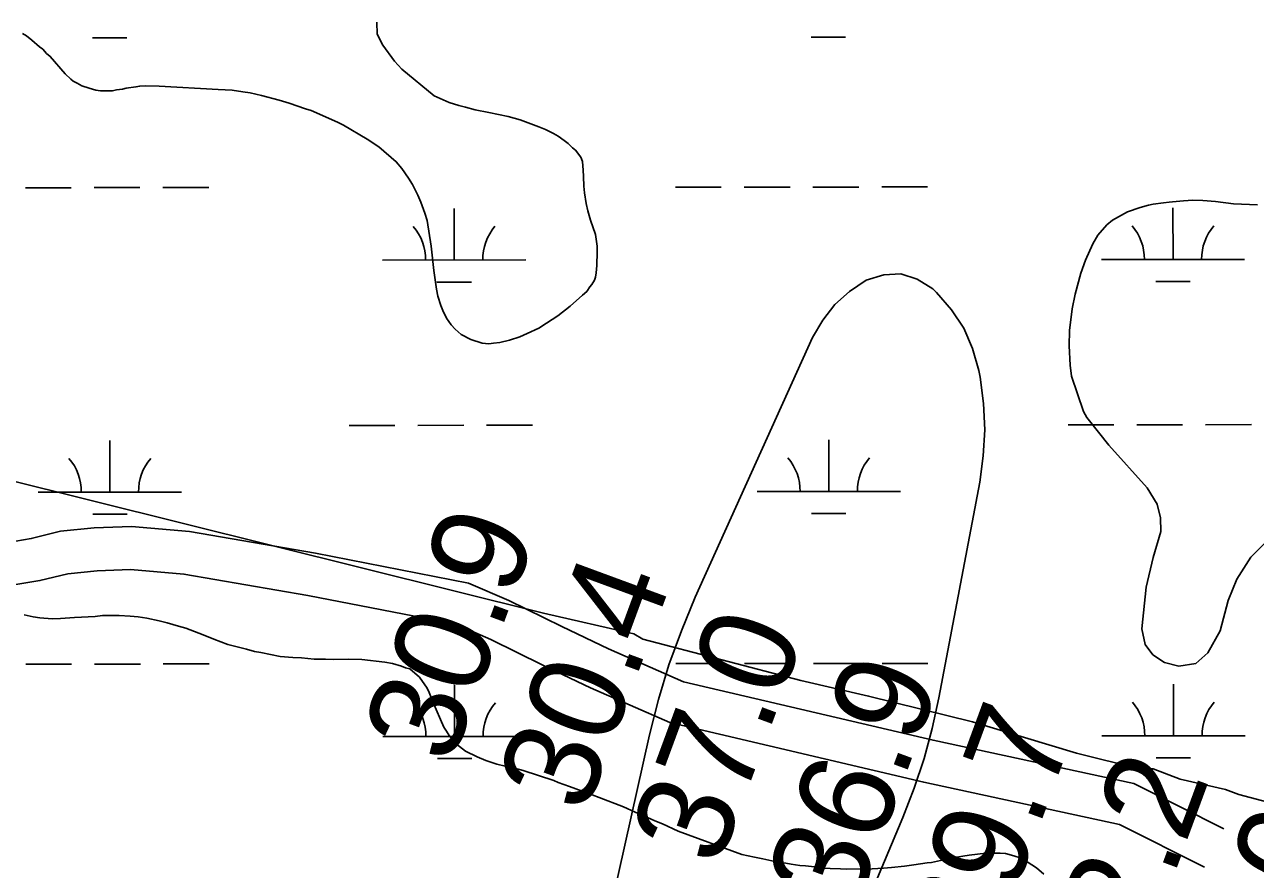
# Model space of a CAD drawing. Extents: x 3297716 to 3335574, y 688621 to 713991.
# Drawn here: x 3319550 to 3320409, y 696104 to 696694 of the extents above; entities that cross this region are included whole.
import ezdxf

# ---------------------------------------------------------------- set-up
doc = ezdxf.new("R2010")
doc.units = 0
for name, color, linetype in [('V-RIVR-EDGE', 7, 'Continuous'), ('V-RIVR-RANG', 7, 'Continuous'), ('V-ROAD-CNTR', 7, 'Continuous'), ('V-SITE-VEGE', 7, 'Continuous'), ('V-TOPO-MINR', 7, 'Continuous'), ('V-UTIL-LINE', 7, 'Continuous'), ('V-WETL-SWMP', 7, 'Continuous')]:
    doc.layers.add(name, color=color, linetype=linetype)

msp = doc.modelspace()

# ---------------------------------------------------------------- linework, layer by layer
at = {"layer": 'V-RIVR-EDGE'}
msp.add_spline([(3321618.45, 701061.3), (3321639.17, 701040.92), (3321661.92, 701020.55), (3321674.32, 701007.67), (3321694.16, 700986.07), (3321717.72, 700957.41), (3321720.61, 700953.26), (3321724.75, 700950.76), (3321726.82, 700949.51), (3321730.12, 700946.19), (3321742.93, 700927.09), (3321753.65, 700905.93), (3321756.11, 700893.9), (3321759.81, 700884.36), (3321768.06, 700867.34), (3321776.73, 700853.23), (3321786.64, 700837.46), (3321794.49, 700827.9), (3321804.41, 700817.1), (3321812.69, 700810.04), (3321821.8, 700809.18), (3321830.09, 700806.68), (3321833.39, 700803.77), (3321835.87, 700798.79), (3321840.83, 700792.97), (3321849.52, 700787.56), (3321852, 700783.83), (3321866.46, 700765.14), (3321875.54, 700751.02), (3321880.08, 700741.06), (3321885.01, 700725.72), (3321889.55, 700717), (3321895.75, 700710.35), (3321901.94, 700699.15), (3321908.12, 700684.63), (3321912.22, 700664.31), (3321919.16, 700623.67), (3321922, 700598.79), (3321922.33, 700564.8), (3321921.8, 700517.55), (3321919.28, 700502.22), (3321912.99, 700476.13), (3321905.84, 700433.04), (3321899.49, 700379.59), (3321893.61, 700348.1), (3321887.31, 700316.2), (3321880.2, 700288.86), (3321874.74, 700259.03), (3321869.25, 700218.84), (3321863.73, 700164.56), (3321860.77, 700141.35), (3321859.51, 700133.9), (3321857.38, 700109.86), (3321857.72, 700080.85), (3321854.3, 700038.58), (3321847.95, 699987.61), (3321847.83, 699937.46), (3321848.6, 699913.83), (3321849.33, 699873.21), (3321853.78, 699830.51), (3321854.96, 699803.15), (3321853.26, 699786.99), (3321851.54, 699762.54), (3321847.36, 699747.63), (3321844.45, 699743.9), (3321843.17, 699728.57), (3321839.41, 699718.22), (3321831.1, 699708.71), (3321827.36, 699705.81), (3321826.94, 699701.67), (3321826.9, 699687.16), (3321823.15, 699678.88), (3321813.6, 699670.62), (3321798.66, 699664.44), (3321785.76, 699644.16), (3321779.93, 699632.57), (3321773.21, 699598.6), (3321768.1, 699540.58), (3321765.15, 699519.86), (3321762.59, 699492.93), (3321757.53, 699458.54), (3321751.27, 699439.49), (3321741.26, 699415.47), (3321732.08, 699391.04), (3321722.08, 699368.27), (3321716.24, 699354.61), (3321712.46, 699334.72), (3321711.17, 699313.17), (3321708.16, 699269.24), (3321710.2, 699258.88), (3321713.08, 699250.99), (3321718.86, 699240.62), (3321727.54, 699231.89), (3321733.75, 699226.9), (3321735.8, 699219.85), (3321729.5, 699186.29), (3321720.32, 699159.37), (3321709.07, 699134.53), (3321700.31, 699115.49), (3321685.36, 699100.6), (3321679.12, 699094.4), (3321674.96, 699087.37), (3321674.54, 699083.64), (3321670.34, 699063.75), (3321660.32, 699031.86), (3321651.17, 699018.62), (3321638.28, 699002.49), (3321632.02, 698987.58), (3321625.76, 698968.12), (3321619.46, 698936.22), (3321615.66, 698908.04), (3321607.29, 698875.32), (3321593.49, 698825.61), (3321583.49, 698805.33), (3321580.14, 698792.07), (3321580.11, 698777.57), (3321580.08, 698768.03), (3321572.16, 698748.16), (3321567.94, 698717.91), (3321559.1, 698663.64), (3321555.74, 698647.06), (3321554.07, 698638.36), (3321550.73, 698631.74), (3321551.53, 698617.65), (3321548.59, 698601.9), (3321548.13, 698586.15), (3321543.97, 698577.46), (3321538.14, 698566.28), (3321534.37, 698551.37), (3321535.17, 698541.42), (3321533.49, 698532.72), (3321521.4, 698502.08), (3321503.45, 698451.14), (3321490.53, 698421.75), (3321481.38, 698409.33), (3321476.81, 698403.96), (3321474.3, 698395.26), (3321466.79, 698374.55), (3321458.45, 698355.09), (3321454.28, 698343.91), (3321453.02, 698339.36), (3321455.92, 698336.45), (3321456.74, 698333.13), (3321454.65, 698329.4), (3321448.83, 698321.96), (3321440.11, 698313.69), (3321430.98, 698308.32), (3321420.6, 698301.3), (3321418.1, 698296.34), (3321412.68, 698284.33), (3321407.28, 698277.71), (3321395.61, 698252.46), (3321375.16, 698198.21), (3321359.31, 698158.46), (3321345.97, 698126.16), (3321337.19, 698093.85), (3321334.25, 698078.94), (3321334.23, 698070.24), (3321336.69, 698059.45), (3321328.74, 698032.12), (3321314.56, 697996.09), (3321306.62, 697968.76), (3321301.21, 697958.41), (3321293.31, 697951.38), (3321284.15, 697933.99), (3321274.57, 697915.37), (3321271.23, 697904.6), (3321272.45, 697893.82), (3321272.42, 697881.8), (3321266.57, 697862.33), (3321256.95, 697828.37), (3321254.44, 697817.6), (3321249.85, 697808.08), (3321241.51, 697787.79), (3321233.61, 697774.54), (3321226.53, 697762.13), (3321220.27, 697745.56), (3321216.1, 697733.97), (3321215.67, 697727.34), (3321217.73, 697725.67), (3321219.8, 697723.6), (3321219.37, 697718.62), (3321208.12, 697691.71), (3321197.7, 697668.11), (3321194.79, 697666.04), (3321191.06, 697666.05), (3321191.45, 697656.52), (3321188.95, 697651.55), (3321185.63, 697649.07), (3321180.24, 697647.84), (3321181.04, 697635.82), (3321179.37, 697630.85), (3321174.8, 697625.89), (3321172.29, 697619.26), (3321170.2, 697612.22), (3321164.33, 697585.71), (3321162.65, 697577.01), (3321158.92, 697575.78), (3321154.35, 697570.81), (3321148.51, 697557.56), (3321144.77, 697550.53), (3321143.91, 697539.34), (3321140.58, 697535.62), (3321134.77, 697529.41), (3321132.68, 697525.27), (3321128.5, 697509.53), (3321122.64, 697486.75), (3321103.06, 697447.42), (3321100.98, 697441.63), (3321100.95, 697432.92), (3321091.79, 697415.12), (3321084.3, 697404.36), (3321071.4, 697382.01), (3321064.34, 697376.64), (3321056.87, 697372.93), (3321048.14, 697363.42), (3321041.07, 697351), (3321031.9, 697332.37), (3321023.56, 697312.08), (3321015.63, 697288.06), (3321006.43, 697254.51), (3320994.76, 697229.67), (3320983.51, 697207.32), (3320979.36, 697203.6), (3320975.6, 697193.66), (3320968.09, 697172.54), (3320962.64, 697145.61), (3320955.95, 697122.42), (3320943.84, 697086.8), (3320940.48, 697069.4), (3320936.31, 697061.12), (3320926.34, 697048.71), (3320920.93, 697043.34), (3320909.64, 697002.33), (3320899.61, 696969.2), (3320887.51, 696935.24), (3320880.84, 696920.33), (3320879.58, 696912.46), (3320883.28, 696900.43), (3320882.85, 696894.63), (3320876.18, 696878.07), (3320871.56, 696854.04), (3320866.95, 696835.81), (3320859.86, 696815.94), (3320857.35, 696806.82), (3320853.17, 696794.4), (3320849.83, 696784.46), (3320847.3, 696766.64), (3320843.13, 696755.46), (3320836.06, 696746.78), (3320830.23, 696736.43), (3320825.62, 696714.06), (3320819.78, 696699.98), (3320814.39, 696700.82), (3320813.53, 696688.39), (3320798.51, 696648.22), (3320788.51, 696625.45), (3320782.7, 696621.73), (3320776.44, 696606.83), (3320773.11, 696599.38), (3320766.05, 696592.76), (3320752.32, 696573.31), (3320739.41, 696550.14), (3320720.25, 696512.05), (3320700.68, 696473.55), (3320668.58, 696401.51), (3320646.49, 696351.83), (3320619.82, 696291.38), (3320606.9, 696264.05), (3320587.72, 696216.85), (3320576.88, 696191.59), (3320559.79, 696152.26), (3320552.68, 696128.24), (3320546.41, 696106.29), (3320536.39, 696076.47), (3320526.77, 696040.43), (3320506.73, 695984.11), (3320462.47, 695850.34), (3320450.34, 695806.02), (3320441.99, 695784.08), (3320420.24, 695702.06), (3320413.95, 695672.23), (3320409.31, 695639.92), (3320408.02, 695624.17), (3320406.74, 695608.42), (3320408.37, 695594.32), (3320410.83, 695583.96), (3320416.18, 695571.92), (3320421.98, 695567.35), (3320430.26, 695563.18), (3320436.88, 695558.19), (3320439.76, 695552.38), (3320445.95, 695539.93), (3320448.82, 695529.15), (3320449.62, 695514.64), (3320448.35, 695507.18), (3320445.85, 695499.32), (3320439.61, 695490.63), (3320432.95, 695478.62), (3320425.04, 695464.14), (3320423.36, 695454.61), (3320416.68, 695438.87), (3320407.94, 695423.56), (3320400.05, 695416.95), (3320392.16, 695411.99), (3320377.64, 695405.4), (3320369.77, 695408.32), (3320357.76, 695410.42), (3320346.57, 695411.28), (3320320.43, 695400.15), (3320298.01, 695386.53), (3320249, 695343.13), (3320201.63, 695295.58), (3320188.34, 695286.49), (3320177.97, 695282.37), (3320168.43, 695279.5), (3320163.44, 695274.95), (3320158.02, 695258.8), (3320150.48, 695228.14), (3320140.07, 695207.45), (3320125.48, 695174.32), (3320115.05, 695149.48), (3320110.04, 695134.99), (3320108.37, 695129.6), (3320108.36, 695125.87), (3320112.48, 695115.91), (3320113.71, 695108.45), (3320113.28, 695102.65), (3320106.62, 695091.47), (3320104.12, 695086.92), (3320100.38, 695081.54), (3320098.3, 695077.82), (3320098.29, 695074.91), (3320104.89, 695063.71), (3320105.7, 695055.41), (3320108.15, 695041.32), (3320112.69, 695030.11), (3320122.19, 695016.41), (3320128.39, 695010.18), (3320133.76, 695004.36), (3320135.82, 694999.39), (3320135.81, 694993.17), (3320132.46, 694981.16), (3320110.39, 694941.42), (3320095, 694917.83), (3320080.04, 694902.95), (3320068.41, 694893.44), (3320055.95, 694881.45), (3320033.07, 694848.77), (3319991.89, 694787.94), (3319966.93, 694752.36), (3319939.88, 694710.15), (3319919.91, 694678.69), (3319900.35, 694647.24), (3319884.95, 694618.27), (3319831.21, 694511.88), (3319802.89, 694453.92), (3319782.47, 694411.28), (3319716.3, 694301.19), (3319680.91, 694240.35), (3319651.35, 694187.37), (3319580.16, 694059.05), (3319556.78, 694017.46)], degree=3, dxfattribs=at)
at = {"layer": 'V-ROAD-CNTR'}
for points in [[(3319258.98, 696423.67), (3319303.18, 696420.44), (3319359.75, 696407.56), (3319427.13, 696378.13), (3319493.56, 696347.28), (3319522.29, 696338.92), (3319543.92, 696333.5), (3319554.75, 696335.31), (3319575.26, 696340.4), (3319598.65, 696342.78), (3319624.79, 696343.71), (3319665.22, 696340.25), (3319753.28, 696325.06), (3319860.04, 696304.26), (3319888.31, 696292.15), (3319925.18, 696273.99), (3319957.8, 696258.37), (3320010.26, 696235.36), (3320184.45, 696194.42), (3320324.59, 696164.24), (3320387.39, 696132.69)], [(3319256.79, 696393.75), (3319298.74, 696390.69), (3319350.33, 696378.94), (3319414.81, 696350.77), (3319482.99, 696319.11), (3319514.45, 696309.96), (3319542.7, 696302.88), (3319560.85, 696305.91), (3319580.42, 696310.77), (3319600.71, 696312.84), (3319624.04, 696313.66), (3319661.38, 696310.47), (3319747.86, 696295.55), (3319851.17, 696275.43), (3319875.76, 696264.88), (3319912.07, 696247), (3319945.29, 696231.09), (3320000.73, 696206.78), (3320177.86, 696165.15), (3320314.54, 696135.71), (3320373.92, 696105.88)]]:
    msp.add_lwpolyline(points, dxfattribs=at)
at = {"layer": 'V-SITE-VEGE'}
for p, q in [((3319549.9, 696282), (3319556.09, 696280.64)), ((3319556.09, 696280.64), (3319560.88, 696279.83)), ((3319560.88, 696279.83), (3319569.32, 696279.33)), ((3319569.32, 696279.33), (3319575.23, 696279.37)), ((3319575.23, 696279.37), (3319585.06, 696280.29)), ((3319585.06, 696280.29), (3319599.4, 696280.95)), ((3319599.4, 696280.95), (3319604.45, 696281.55)), ((3319604.45, 696281.55), (3319616.27, 696281.64)), ((3319616.27, 696281.64), (3319623.86, 696281.13)), ((3319623.86, 696281.13), (3319629.49, 696280.61)), ((3319629.49, 696280.61), (3319635.4, 696279.81)), ((3319635.4, 696279.81), (3319644.13, 696277.9)), ((3319644.13, 696277.9), (3319649.76, 696276.54)), ((3319649.76, 696276.54), (3319657.66, 696274.06)), ((3319657.66, 696274.06), (3319662.73, 696272.69)), ((3319662.73, 696272.69), (3319674.85, 696268)), ((3319674.85, 696268), (3319682.19, 696264.96)), ((3319682.19, 696264.96), (3319692.06, 696261.38)), ((3319692.06, 696261.38), (3319701.35, 696258.91)), ((3319701.35, 696258.91), (3319705.02, 696258.1)), ((3319705.02, 696258.1), (3319710.65, 696256.45)), ((3319710.65, 696256.45), (3319715.15, 696255.64)), ((3319715.15, 696255.64), (3319728.67, 696252.93)), ((3319728.67, 696252.93), (3319737.4, 696252.15)), ((3319737.4, 696252.15), (3319743.58, 696251.91)), ((3319743.58, 696251.91), (3319752.31, 696251.13)), ((3319752.31, 696251.13), (3319760.18, 696251.18)), ((3319760.18, 696251.18), (3319765.53, 696250.94)), ((3319765.53, 696250.94), (3319776.21, 696251.02)), ((3319776.21, 696251.02), (3319785.49, 696250.81)), ((3319785.49, 696250.81), (3319801.54, 696248.96)), ((3319801.54, 696248.96), (3319806.89, 696248.15)), ((3319806.89, 696248.15), (3319813.37, 696246.23)), ((3319813.37, 696246.23), (3319816.19, 696245.12)), ((3319816.19, 696245.12), (3319819, 696244.3)), ((3319819, 696244.3), (3319825.79, 696238.44)), ((3319825.79, 696238.44), (3319831.19, 696230.89)), ((3319831.19, 696230.89), (3319832.62, 696227.81)), ((3319832.62, 696227.81), (3319835.2, 696221.36)), ((3319835.2, 696221.36), (3319842.92, 696203.7)), ((3319842.92, 696203.7), (3319844.63, 696200.9)), ((3319844.63, 696200.9), (3319846.62, 696197.82)), ((3319846.62, 696197.82), (3319848.03, 696196.14)), ((3319848.03, 696196.14), (3319849.74, 696193.62)), ((3319849.74, 696193.62), (3319851.72, 696191.67)), ((3319851.72, 696191.67), (3319857.95, 696186.93)), ((3319857.95, 696186.93), (3319866.13, 696182.78)), ((3319866.13, 696182.78), (3319872.05, 696180.29)), ((3319872.05, 696180.29), (3319879.95, 696177.82)), ((3319879.95, 696177.82), (3319885.58, 696176.45)), ((3319885.58, 696176.45), (3319889.52, 696175.64)), ((3319889.52, 696175.64), (3319898.25, 696173.45)), ((3319898.25, 696173.45), (3319919.68, 696166.29)), ((3319919.68, 696166.29), (3319922.78, 696164.91)), ((3319922.78, 696164.91), (3319930.67, 696162.15)), ((3319930.67, 696162.15), (3319943.93, 696157.19)), ((3319943.93, 696157.19), (3319946.46, 696156.36)), ((3319946.46, 696156.36), (3319951.26, 696154.43)), ((3319951.26, 696154.43), (3319968.18, 696148.08)), ((3319968.18, 696148.08), (3319976.36, 696144.21)), ((3319976.36, 696144.21), (3319982, 696142)), ((3319982, 696142), (3319990.18, 696138.12)), ((3319990.18, 696138.12), (3319995.54, 696136.19)), ((3319995.54, 696136.19), (3320006.55, 696130.93)), ((3320006.55, 696130.93), (3320050.81, 696114.66)), ((3320209.7, 696114.12), (3320221.22, 696115.61)), ((3320221.22, 696115.61), (3320231.34, 696115.68)), ((3320231.34, 696115.68), (3320235, 696115.43)), ((3320050.81, 696114.66), (3320059.83, 696112.75)), ((3320059.83, 696112.75), (3320065.46, 696111.67)), ((3320065.46, 696111.67), (3320073.91, 696109.76)), ((3320073.91, 696109.76), (3320081.51, 696108.69)), ((3320081.51, 696108.69), (3320085.45, 696107.88)), ((3320085.45, 696107.88), (3320091.36, 696107.08)), ((3320091.36, 696107.08), (3320095.3, 696106.83)), ((3320164.48, 696106.48), (3320170.94, 696107.37)), ((3320170.94, 696107.37), (3320180.21, 696108.85)), ((3320180.21, 696108.85), (3320183.3, 696109.15)), ((3320183.3, 696109.15), (3320191.73, 696110.9)), ((3320191.73, 696110.9), (3320199.3, 696112.64)), ((3320199.3, 696112.64), (3320209.7, 696114.12)), ((3320235, 696115.43), (3320240.92, 696113.79)), ((3320240.92, 696113.79), (3320245.14, 696112.41)), ((3320245.14, 696112.41), (3320250.22, 696109.63)), ((3320250.22, 696109.63), (3320256.72, 696105.46)), ((3320095.3, 696106.83), (3320099.52, 696106.29)), ((3320099.52, 696106.29), (3320103.18, 696106.04)), ((3320103.18, 696106.04), (3320108.81, 696105.24)), ((3320108.81, 696105.24), (3320112.47, 696104.98)), ((3320112.47, 696104.98), (3320119.78, 696104.75)), ((3320119.78, 696104.75), (3320124, 696104.5)), ((3320124, 696104.5), (3320142, 696104.63)), ((3320142, 696104.63), (3320149.87, 696105.25)), ((3320149.87, 696105.25), (3320155.49, 696105.57)), ((3320155.49, 696105.57), (3320164.48, 696106.48)), ((3320256.72, 696105.46), (3320261.78, 696100.96))]:
    msp.add_line(p, q, dxfattribs=at)
for points in [[(3319795.95, 696695.84), (3319796.28, 696687.6), (3319800.19, 696679.94), (3319808.51, 696668.73), (3319813.5, 696662.99), (3319836.17, 696644.47), (3319846.65, 696639.87), (3319853.26, 696637.72), (3319857.94, 696636.66), (3319864.82, 696634.79), (3319874.18, 696632.93), (3319887.67, 696630.01), (3319896.2, 696627.59), (3319909.15, 696622.74), (3319913.84, 696620.85), (3319919.36, 696618.14), (3319922.67, 696616.24), (3319926.81, 696613.25), (3319929.58, 696611.07), (3319932.62, 696608.07), (3319934.83, 696606.44), (3319938.44, 696601.52), (3319939.56, 696598.5), (3319940.15, 696592.46), (3319940.46, 696588.07), (3319940.51, 696581.47), (3319941.09, 696576.8), (3319942.25, 696569.39), (3319943.38, 696564.18), (3319945.35, 696557.6), (3319948.72, 696547.73), (3319949.3, 696544.43), (3319949.88, 696539.49), (3319949.93, 696532.9), (3319949.69, 696528.5), (3319949.7, 696526.02), (3319949.19, 696520.8), (3319948.67, 696517.77), (3319948.13, 696515.84), (3319946.23, 696512.81), (3319944.87, 696511.15), (3319942.69, 696507.83), (3319939.69, 696505.34), (3319930.95, 696497.58), (3319922.48, 696490.92), (3319914.54, 696485.64), (3319909.07, 696482.31), (3319901.13, 696478.4), (3319895.93, 696476.17), (3319888.8, 696473.92)], [(3319888.8, 696473.92), (3319881.94, 696472.22), (3319877.54, 696471.64), (3319874.25, 696471.34), (3319869.57, 696471.85), (3319861.59, 696474.27), (3319854.97, 696477.79), (3319850.82, 696481.61), (3319848.05, 696484.61), (3319844.72, 696489.26), (3319842.21, 696494.46), (3319840.8, 696498.03), (3319838.56, 696504.61), (3319837.7, 696509.55), (3319835.95, 696522.45), (3319833.91, 696539.47), (3319831.31, 696557.32), (3319829.62, 696562.53), (3319826.81, 696570.2), (3319824.58, 696575.13), (3319820.96, 696582.53), (3319818.17, 696586.9), (3319813.45, 696593.74), (3319809.57, 696598.38), (3319797.41, 696608.74), (3319789.4, 696614.18), (3319772.83, 696623.95), (3319768.7, 696626.12), (3319750.23, 696634.23), (3319746.37, 696635.3), (3319734.8, 696639.34), (3319727.91, 696641.49), (3319715.52, 696644.7), (3319707.54, 696646.56), (3319702.59, 696647.35), (3319695.16, 696648.4), (3319685.26, 696648.87), (3319644.02, 696651.32), (3319634.4, 696651.53), (3319630.56, 696651.23), (3319627.81, 696650.66), (3319620.95, 696649.78), (3319618.48, 696649.21), (3319614.36, 696648.64), (3319611.62, 696648.06), (3319603.1, 696648), (3319599.79, 696648.53), (3319595.11, 696649.87), (3319590.16, 696651.48), (3319586.84, 696653.38), (3319584.08, 696654.74), (3319582.43, 696656.1), (3319578.55, 696659.92), (3319568.02, 696671.93), (3319565.53, 696674.11), (3319562.76, 696677.12), (3319560.55, 696678.75), (3319555.3, 696683.38), (3319551.43, 696686.38), (3319548.67, 696688.01)], [(3320421.74, 696337.7), (3320406.21, 696322.24), (3320396.53, 696306.97), (3320390.35, 696292.16), (3320384.8, 696270.93), (3320376.15, 696255.52), (3320367.87, 696248), (3320356.04, 696246.17), (3320346.09, 696248.72), (3320337.86, 696254.22), (3320332.4, 696261.34), (3320330.13, 696272.29), (3320333.28, 696301.25), (3320338.1, 696322.18), (3320343.38, 696340.2), (3320343.31, 696349.7), (3320340.9, 696359.33), (3320333.95, 696370.68), (3320307.13, 696400.45), (3320291.89, 696419.76), (3320289.56, 696424.02), (3320281.16, 696448.62), (3320280.11, 696456.5), (3320279.36, 696469.98), (3320279.61, 696480.51), (3320281.47, 696495.65), (3320283.7, 696505.86), (3320287.54, 696520.69), (3320290.77, 696529.59), (3320295.95, 696541.14), (3320299.52, 696547.08), (3320305.71, 696554.36), (3320309.64, 696557.68), (3320320.12, 696563.35), (3320328.98, 696566.37), (3320334.89, 696568.06), (3320338.17, 696568.74), (3320345.4, 696569.78), (3320349.34, 696570.14), (3320351.64, 696570.48), (3320359.2, 696571.2), (3320365.77, 696571.57), (3320372.68, 696571.29), (3320381.57, 696570.7), (3320394.07, 696569.14), (3320410.85, 696568.28)]]:
    msp.add_lwpolyline(points, dxfattribs=at)
at = {"layer": 'V-TOPO-MINR'}
msp.add_lwpolyline([(3319956.35, 696063.9), (3319986.36, 696198.23), (3319992.65, 696222.82), (3319999.93, 696247.08), (3320008.68, 696270.85), (3320018.41, 696294.29), (3320100.34, 696475.7), (3320107.37, 696487.87), (3320115.72, 696498.8), (3320126.05, 696507.89), (3320137.7, 696515.75), (3320150.02, 696519.46), (3320161.93, 696520.18), (3320173.25, 696516.38), (3320184.17, 696509.58), (3320186.81, 696507.08), (3320197.22, 696495.13), (3320205.9, 696482.24), (3320212, 696467.95), (3320216.36, 696452.71), (3320217.23, 696448.01), (3320219.57, 696429.66), (3320220.55, 696411.31), (3320219.48, 696392.96), (3320217.06, 696374.62), (3320188.51, 696224.09), (3320183.77, 696202.76), (3320178.15, 696181.69), (3320171.21, 696161.01), (3320163.4, 696140.6), (3320118.27, 696032.94)], dxfattribs=at)
at = {"layer": 'V-UTIL-LINE'}
msp.add_lwpolyline([(3320520.98, 696123.89), (3320397.99, 696156.48), (3320388.53, 696160.12), (3320357.02, 696167.34), (3320338.1, 696174.6), (3320328.64, 696174.59), (3320284.5, 696185.45), (3320211.96, 696207.21), (3320139.45, 696225.32), (3320092.12, 696236.18), (3319981.78, 696265.15), (3319975.47, 696268.78), (3319912.39, 696283.27), (3319534.06, 696377.43)], dxfattribs=at)
at = {"layer": 'V-WETL-SWMP'}
for p, q in [((3319597.43, 696684.99), (3319621.43, 696685.01)), ((3320099.34, 696685.41), (3320123.34, 696685.43)), ((3319550.68, 696580.31), (3319582.68, 696580.33)), ((3319598.68, 696580.35), (3319630.68, 696580.37)), ((3319646.68, 696580.39), (3319678.68, 696580.41)), ((3320004.58, 696580.69), (3320036.58, 696580.71)), ((3320052.58, 696580.73), (3320084.58, 696580.75)), ((3320100.58, 696580.77), (3320132.58, 696580.79)), ((3320148.58, 696580.81), (3320180.58, 696580.83)), ((3319850.03, 696529.82), (3319850, 696565.82)), ((3320351.94, 696530.24), (3320351.91, 696566.24)), ((3319800.03, 696529.77), (3319900.03, 696529.86)), ((3320301.94, 696530.19), (3320401.94, 696530.28)), ((3319838.05, 696514.37), (3319862.05, 696514.39)), ((3320339.95, 696514.8), (3320363.95, 696514.82)), ((3319776.72, 696414.32), (3319808.72, 696414.35)), ((3319824.72, 696414.36), (3319856.72, 696414.39)), ((3319872.72, 696414.4), (3319904.72, 696414.43)), ((3320278.63, 696414.74), (3320310.63, 696414.77)), ((3320326.63, 696414.78), (3320358.63, 696414.81)), ((3320374.63, 696414.82), (3320406.63, 696414.85)), ((3319609.7, 696367.75), (3319609.67, 696403.75)), ((3320111.6, 696368.17), (3320111.57, 696404.17)), ((3319559.7, 696367.71), (3319659.7, 696367.79)), ((3320061.6, 696368.13), (3320161.6, 696368.21)), ((3319597.71, 696352.31), (3319621.71, 696352.33)), ((3320099.62, 696352.73), (3320123.62, 696352.75)), ((3319550.96, 696247.63), (3319582.96, 696247.66)), ((3319598.96, 696247.67), (3319630.95, 696247.7)), ((3319646.95, 696247.71), (3319678.95, 696247.74)), ((3320004.86, 696248.01), (3320036.86, 696248.04)), ((3320052.86, 696248.05), (3320084.86, 696248.08)), ((3320100.86, 696248.09), (3320132.86, 696248.12)), ((3320148.86, 696248.13), (3320180.86, 696248.16)), ((3319850.31, 696197.14), (3319850.28, 696233.14)), ((3320352.22, 696197.56), (3320352.19, 696233.56)), ((3319800.31, 696197.1), (3319900.31, 696197.18)), ((3320302.22, 696197.52), (3320402.22, 696197.6)), ((3319838.32, 696181.7), (3319862.32, 696181.72)), ((3320340.23, 696182.12), (3320364.23, 696182.14))]:
    msp.add_line(p, q, dxfattribs=at)
for centre, start, end in [((3320407.18, 696530.76), 139.27624, 180.8199), ((3319794.79, 696530.24), 359.27624, 40.81989), ((3319905.28, 696530.34), 139.27624, 180.8199), ((3320296.7, 696530.66), 359.27624, 40.81989), ((3319554.46, 696368.18), 359.27624, 40.81989), ((3319664.94, 696368.27), 139.27624, 180.8199), ((3320056.36, 696368.6), 359.27624, 40.81989), ((3320166.85, 696368.69), 139.27624, 180.8199), ((3319795.07, 696197.57), 359.27624, 40.81989), ((3319905.55, 696197.66), 139.27624, 180.8199), ((3320296.97, 696197.99), 359.27624, 40.81989), ((3320407.46, 696198.08), 139.27624, 180.8199)]:
    msp.add_arc(centre, 35.25, start, end, dxfattribs=at)

# ---------------------------------------------------------------- texts
at = {"layer": 'V-RIVR-RANG'}
for s, p in [('30.9', (3319847.72, 696175.9)), ('30.4', (3319941.73, 696141.81)), ('37.0', (3320034.64, 696104.74)), ('36.9', (3320129.47, 696072.87)), ('29.7', (3320223.48, 696038.77)), ('32.2', (3320317.4, 696004.42)), ('28.0', (3320410.31, 695967.35))]:
    msp.add_text(s, height=67, rotation=69.76833, dxfattribs=at).set_placement(p)

doc.saveas('drawing.dxf')
